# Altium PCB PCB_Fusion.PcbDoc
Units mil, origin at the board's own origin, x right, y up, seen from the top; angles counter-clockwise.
Board outline 985 x 1775 mil, 2 copper layers (Top Layer, Bottom Layer); 47 components, 34 nets, 181 pads, 49 vias.
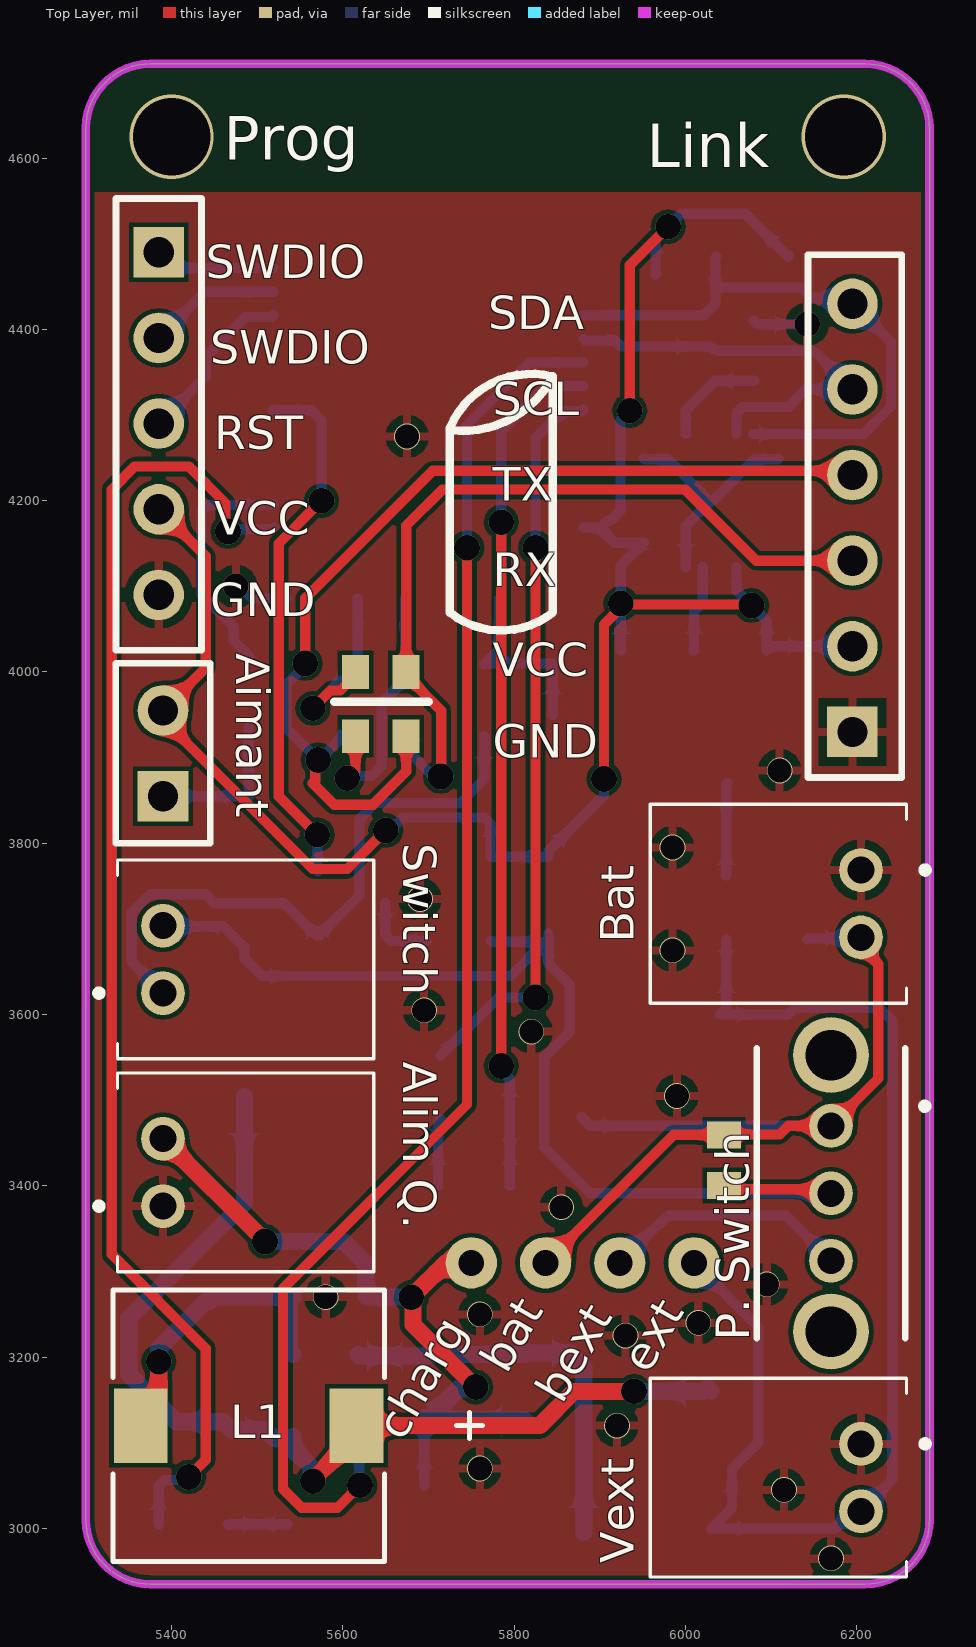
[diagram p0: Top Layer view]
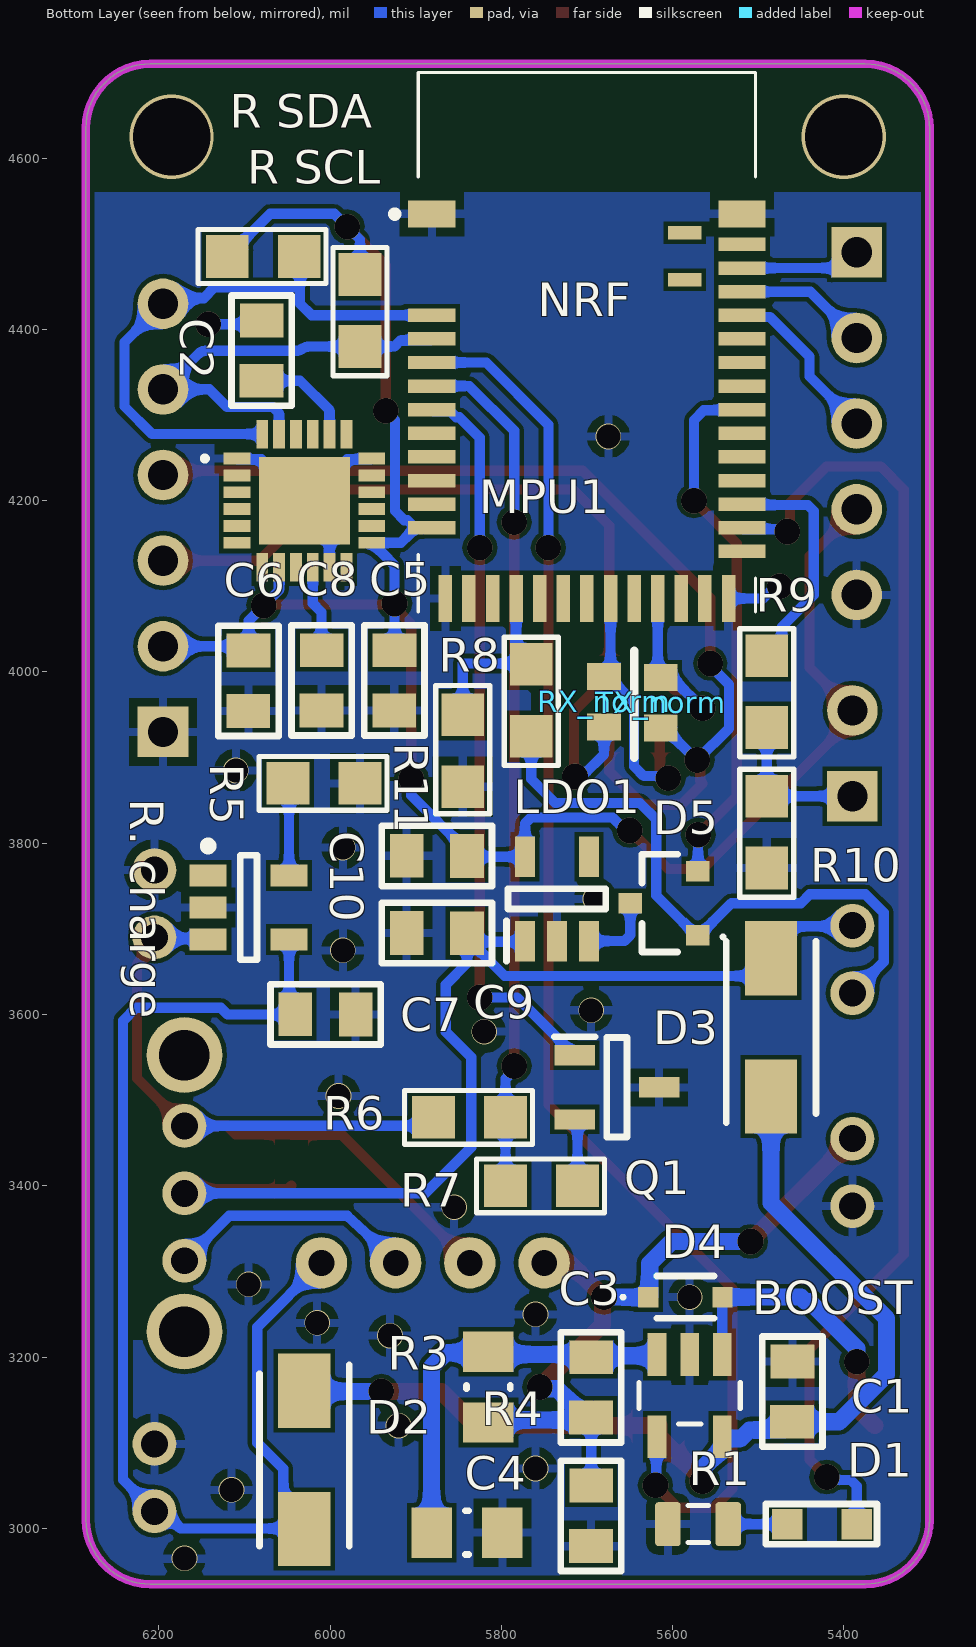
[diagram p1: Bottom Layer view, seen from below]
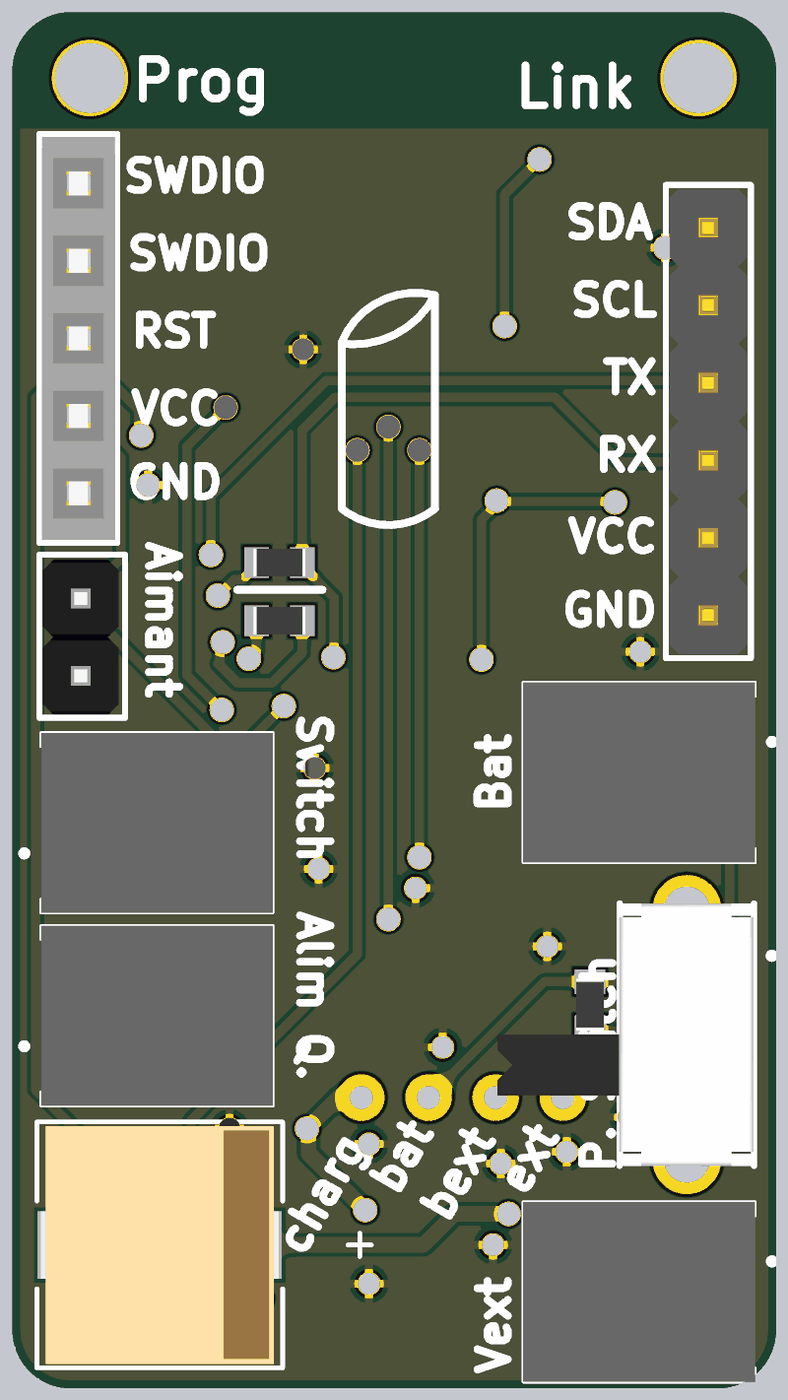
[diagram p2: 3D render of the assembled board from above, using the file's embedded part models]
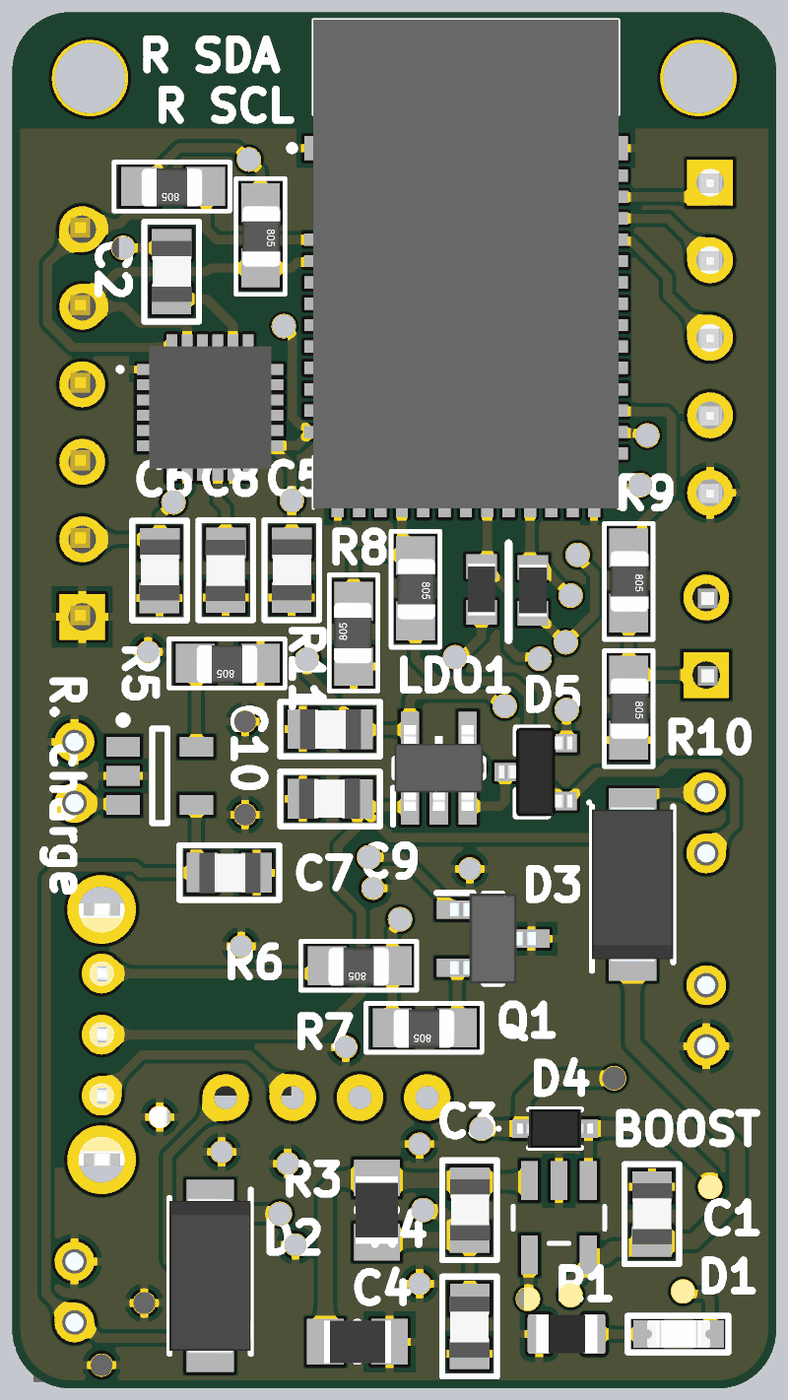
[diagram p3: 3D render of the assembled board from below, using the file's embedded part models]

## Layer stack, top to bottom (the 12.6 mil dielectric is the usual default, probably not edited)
Top Solder: solder mask 0.4, Solder Resist, Dk 3.5
Top Layer: signal copper 1.4
Dielectric 1: dielectric 12.6, FR-4, Dk 4.8
Bottom Layer: signal copper 1.4
Bottom Solder: solder mask 0.4, Solder Resist, Dk 3.5

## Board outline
5300,3010 5300,4635 cw(c5375,4635) 5375,4710 6210,4710 cw(c6210,4635) 6285,4635 6285,3010 cw(c6210,3010) 6210,2935 5375,2935 cw(c5375,3010)

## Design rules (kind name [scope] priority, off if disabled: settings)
Clearance [All] p1: gap=5 ignorepadtopadclearanceinfootprint=FALSE except(10: Arc-Via Track-Via Via-Via; 20: THPad-THPad)
PolygonConnect [All] p1: connectstyle=Relief reliefconductorwidth=10 reliefentries=4 polygonreliefangle="90 Angle" airgapwidth=10
RoutingVias [All] p1: holewidth=30 width=15 viastyle="Through Hole" minholewidth=30 minwidth=15 maxholewidth=40 maxwidth=30
SMDNeckDown [All] p1: percent=50.000
SolderMaskExpansion [All] p1: expansion=4 istentingtop=FALSE
Width [All] p1: maxlimit=20 minlimit=5 preferedwidth=12
30 further rules are at their usual default settings.

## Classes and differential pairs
component class Fusion: BOOST C1 C2 C3 C4 C5 C6 C7 C8 C9 C10 D1 D2 D3 D4 D5 L1 LDO1 MPU1 NRF Q1 R1 R3 R4 R5 R6 R7 R8 R9 R10 R11

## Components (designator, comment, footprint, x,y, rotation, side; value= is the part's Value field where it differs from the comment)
Aimant "JUMPER2" BARRETTE_2_M_D 5390,3855 r90 top (schematic designator "Switch magnetique1")
"Alim Q." "S2B-PH-K-S" S2BPHKS 5390,3376.26 r270 top (schematic designator Connecteur_Alim_Quille1)
Bat "S2B-PH-K-S" S2BPHKS 6205,3768.74 r90 top (schematic designator "Connecteur Bat")
BOOST "LM2735XMF" SOT95P285X110-5N 5580,3155 r270 bottom
C1 "CONDENSATEUR_CMS_CER_0805" CONDENSATEUR_CMS_0805 5460.39,3124.53 r90 bottom value=10uF
C2 "CONDENSATEUR_CMS_CER_0805" CONDENSATEUR_CMS_0805 6080,4340 r90 bottom value=2.2nF
C3 "CONDENSATEUR_CMS_CER_0805" CONDENSATEUR_CMS_0805 5695.39,3129.53 r90 bottom value=330pF
C4 "CONDENSATEUR_CMS_CER_0805" CONDENSATEUR_CMS_0805 5695,3050 r270 bottom value=10uF
C5 "CONDENSATEUR_CMS_CER_0805" CONDENSATEUR_CMS_0805 5925,3955 r90 bottom value=100nF
C6 "CONDENSATEUR_CMS_CER_0805" CONDENSATEUR_CMS_0805 6095.39,3954.53 r90 bottom value=10nF
C7 "CONDENSATEUR_CMS_CER_0805" CONDENSATEUR_CMS_0805 6040.47,3600.39 r180 bottom value=4.7uF
C8 "CONDENSATEUR_CMS_CER_0805" CONDENSATEUR_CMS_0805 6009.61,4025.47 r270 bottom value=100nF
C9 "CONDENSATEUR_CMS_CER_0805" CONDENSATEUR_CMS_0805 5840,3695 r0 bottom value=1uF
C10 "CONDENSATEUR_CMS_CER_0805" CONDENSATEUR_CMS_0805 5910.47,3785.39 r180 bottom value=4.7uF
D1 "LED_CMS_0805" LED_CMS_0805 5385,3005 r270 bottom
D2 "ES1D-E3_61T" DIOM5127X229N 6030,3080 r270 bottom
D3 "ES1D-E3_61T" DIOM5127X229N 5485,3585 r90 bottom
D4 "BAT165AX" BAT165AX 5585,3270 r180 bottom
D5 "BAT54C,215" BAT54C215 5610,3730 r90 bottom
L1 "1234659" IND_123_4659_RSP 5490,3120 r180 top
LDO1 "TPS76333DBVT" SOT95P280X145-5N 5735,3735 r90 bottom
Link "BARRETTE_6 CONTACTS_1 RANGEE_MALE_DROITE" BARRETTE_6_M_D 6195,3930 r90 top (schematic designator "Connecteur link")
MPU1 "MPU-6050" MPU6050 6030,4200 r180 bottom
NRF "MDBT42Q-512KV2" MDBT42Q512KV2 5700,4385 r180 bottom
"P. Switch" "OS102011MA1QN1" OS102011MA1QN1 6170,3391.26 r270 top (schematic designator "Interrupteur glissière?")
Prog "BARRETTE_5 CONTACTS_1 RANGEE_FEMELLE_DROITE" BARRETTE_5_F_D 5385,4490 r270 top (schematic designator "Connecteur prog1")
Q1 "TSM2312CX_RFG" SOT95P280X130-3N 5665,3515 r180 bottom
R1 "Resistor 1K +/-5% 0805 125 mW" RESC0805(2012)_L 5570,3005 r180 bottom value=150
R2 "Resistor 4k7 +/-1% 0603 100 mW" RESC1608X55X25ML10T15 6045,3430 r270 top value=0
R3 "Resistor 10k +/-1% 0805 125 mW" RESC2013X50X35ML15T15 5815,3165 r270 bottom value=3.3k
R4 "Resistor 10k +/-1% 0805 125 mW" RESC2013X50X35ML15T15 5840,2995 r0 bottom value=10k
R5 "RESISTANCE_CMS_0805" RESISTANCE_CMS_0805 5965,3870 r0 bottom value=2
R6 "RESISTANCE_CMS_0805" RESISTANCE_CMS_0805 5795,3480 r0 bottom value=100k
R7 "RESISTANCE_CMS_0805" RESISTANCE_CMS_0805 5711,3400 r0 bottom value=100k
R8 "RESISTANCE_CMS_0805" RESISTANCE_CMS_0805 5765,4009 r270 bottom value=100k
R9 "RESISTANCE_CMS_0805" RESISTANCE_CMS_0805 5490,4019 r270 bottom value=100
R10 "RESISTANCE_CMS_0805" RESISTANCE_CMS_0805 5490,3855 r270 bottom value=10k
R11 "RESISTANCE_CMS_0805" RESISTANCE_CMS_0805 5845,3866 r90 bottom value=100k
"R SCL" "RESISTANCE_CMS_0805" RESISTANCE_CMS_0805 5965,4464 r270 bottom value=10k (schematic designator "PULLUP SCL1")
"R SDA" "RESISTANCE_CMS_0805" RESISTANCE_CMS_0805 6036,4485 r0 bottom value=10k (schematic designator "PULLUP SDA1")
"R. charge" "MCP73831T-2DCI/OT" SOT-23-OT5_N 6095,3725 r180 bottom (schematic designator "Régulateur de charge")
RX_inv "Resistor 4k7 +/-1% 0603 100 mW" RESC1608X55X25ML10T15 5644.37,3925 r0 top value=0
RX_norm "Resistor 4k7 +/-1% 0603 100 mW" RESC1608X55X25ML10T15 5680,3965.47 r90 bottom value=0
Switch "S2B-PH-K-S" S2BPHKS 5390,3625 r270 top (schematic designator "Interrupteur Power")
TX_inv "Resistor 4k7 +/-1% 0603 100 mW" RESC1608X55X25ML10T15 5644.37,4000 r0 top value=0
TX_norm "Resistor 4k7 +/-1% 0603 100 mW" RESC1608X55X25ML10T15 5613.66,3964.13 r90 bottom value=0
Vext "S2B-PH-K-S" S2BPHKS 6205,3098.74 r90 top (schematic designator "Connecteur Vext")

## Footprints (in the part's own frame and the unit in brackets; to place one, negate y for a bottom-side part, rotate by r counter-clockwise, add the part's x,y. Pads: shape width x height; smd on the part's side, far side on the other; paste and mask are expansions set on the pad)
BARRETTE_2_M_D [mm] "BARRETTE 2 CONTACTS ; 1 RANGEE ; DROITE ; MALE ; ESPACEMENT BROCHES = 2.54 mm"
  rect 1.5x1.5 hole 0.9: 1(0,0)
  round 1.5 hole 0.9: 2(2.54,0)
  silkscreen extent -1.4,-1.4 3.94,1.4, body extent -1.3,-1.2 3.78,1.3, height 8.55
BARRETTE_5_F_D [mm] "BARRETTE 5 CONTACTS ; 1 RANGEE ; DROITE ; FEMELLE ; ESPACEMENT BROCHES = 2.54 mm"
  rect 1.5x1.5 hole 0.9: 1(0,0)
  round 1.5 hole 0.9: 2(2.54,0) 3(5.08,0) 4(7.62,0) 5(10.16,0)
  silkscreen extent -1.6,-1.27 11.8,1.27, body extent -1.5,-1.2 11.7,1.21, height 8.5
BARRETTE_6_M_D [mm] "BARRETTE 6 CONTACTS ; 1 RANGEE ; DROITE ; MALE ; ESPACEMENT BROCHES = 2.54 mm"
  rect 1.5x1.5 hole 0.9: 1(0,0)
  round 1.5 hole 0.9: 2(2.54,0) 3(5.08,0) 4(7.62,0) 5(10.16,0) 6(12.7,0)
  silkscreen extent -1.35,-1.46 14.15,1.32, body extent -1.22,-1.34 14.02,1.2, height 10.1
BAT54C215 [mm]
  rect 0.6x0.7 smd: 1(-0.95,-1) 2(0.95,-1) 3(0,1)
  silkscreen extent -1.45,-1.8 1.45,0.65, body extent -1.45,-1.2 1.45,1.2, height 0.95
BAT165AX [mm]
  rect 0.6x0.6 smd: 1(-1.1,0) 2(1.1,0)
  silkscreen extent -1.9,-0.62 0.85,0.62, body extent -1.24,-0.62 1.24,0.63, height 0.93
CONDENSATEUR_CMS_0805 [mm] "CONDENSATEUR CMS 0805 ; DIMENSIONS : 2mm x 1.25mm"
  rect 1x1.3 smd: 1(0,0) 2(1.79,-0.01)
  silkscreen extent -0.74,-0.9 2.53,0.89, body extent -0.09,-0.67 1.91,0.64, height 0.73
DIOM5127X229N [mm]
  rect 2.2x1.55 smd: 1(-2.05,0) 2(2.05,0)
  silkscreen extent -2.82,-1.33 2.55,1.33, body extent -2.55,-1.33 2.55,1.33, height 2.29
IND_123_4659_RSP [mil]
  rect 63x87 smd paste+0 mask+0: 1(-126,0) 2(126,0)
  silkscreen extent -273,-159 159,159, body extent -154,-154 154,154, height 199
LED_CMS_0805 [mm] "LED CMS 0805 ; DIMENSIONS : 2.0mm x 0.9mm"
  rect 0.9x0.9 smd: 1(0,0) 2(0,-2.062)
  silkscreen extent -0.6,-2.7 0.6,0.6, body extent -0.45,-2.06 0.45,0, height 0.85
MDBT42Q512KV2 [mm]
  rect 1.4x0.8 smd: 1(-4.6,3.8) 39(4.6,3.8)
  rect 1.4x0.4 smd: 2(-4.6,0.8) 3(-4.6,0.1) 4(-4.6,-0.6) 5(-4.6,-1.3) 6(-4.6,-2) 7(-4.6,-2.7) 8(-4.6,-3.4) 9(-4.6,-4.1) 10(-4.6,-4.8) 11(-4.6,-5.5) 25(4.6,-6.2) 26(4.6,-5.5) 27(4.6,-4.8) 28(4.6,-4.1) 29(4.6,-3.4) 30(4.6,-2.7) 31(4.6,-2) 32(4.6,-1.3) 33(4.6,-0.6) 34(4.6,0.1) 35(4.6,0.8) 36(4.6,1.5) 37(4.6,2.2) 38(4.6,2.9)
  rect 0.4x1.4 smd: 12(-4.2,-7.6) 13(-3.5,-7.6) 14(-2.8,-7.6) 15(-2.1,-7.6) 16(-1.4,-7.6) 17(-0.7,-7.6) 18(0,-7.6) 19(0.7,-7.6) 20(1.4,-7.6) 21(2.1,-7.6) 22(2.8,-7.6) 23(3.5,-7.6) 24(4.2,-7.6)
  rect 1x0.4 smd: 40(2.9,3.25) 41(2.9,1.85)
  silkscreen extent -5.8,-8 5,8, body extent -5,-8 5,8, height 2.3
MPU6050 [mm]
  rect 0.8x0.35 smd: 1(-2,1.25) 2(-2,0.75) 3(-2,0.25) 4(-2,-0.25) 5(-2,-0.75) 6(-2,-1.25) 13(2,-1.25) 14(2,-0.75) 15(2,-0.25) 16(2,0.25) 17(2,0.75) 18(2,1.25)
  rect 0.35x0.85 smd: 7(-1.25,-1.975) 8(-0.75,-1.975) 9(-0.25,-1.975) 10(0.25,-1.975) 11(0.75,-1.975) 12(1.25,-1.975) 19(1.25,1.975) 20(0.75,1.975) 21(0.25,1.975) 22(-0.25,1.975) 23(-0.75,1.975) 24(-1.25,1.975)
  rect 2.7x2.6 smd: 25(0,0)
  silkscreen extent -3,1.2 -2.9,1.3, body extent -2,-2 2,2, height 0.88
OS102011MA1QN1 [mm]
  round 1.3 hole 0.8: 1(-2,0) 2(0,0) 3(2,0)
  round 2.25 hole 1.5: 4(-4.1,0) 5(4.1,0)
  silkscreen extent -4.3,-2.2 4.3,2.88, body extent -4.3,-6.22 4.3,2.18, height 4.59
RESC0805(2012)_L [mm] "Chip Resistor, Body 2.0x1.3mm, IPC High Density"
  rrect25% 0.76x1.3 smd: 1(-0.9,0) 2(0.89,0)
  silkscreen extent -0.3,-0.55 0.3,0.55, body extent -1,-0.62 1,0.63, height 0.6
RESC1608X55X25ML10T15 [mm] "Chip Resistor, 2-Leads, Body 1.70x0.90mm, IPC Low Density"
  rect 0.8x1 smd: 1(-0.75,0) 2(0.75,0)
  body extent -0.85,-0.45 0.85,0.45, height 0.55
RESC2013X50X35ML15T15 [mm] "Chip Resistor, 2-Leads, Body 2.2x1.4mm, IPC Low Density"
  rect 1.2x1.5 smd: 1(-1.05,0) 2(1.05,0)
  silkscreen extent -0.05,-0.65 0.05,0.65, body extent -1.1,-0.7 1.1,0.7, height 0.5
RESISTANCE_CMS_0805 [mil] "RESISTANCE CMS 0805 ; DIMENSIONS : 2mm x 1.25mm"
  rect 50x50 smd: 1(0,0) 2(84,0)
  silkscreen extent -31,-31 118,31, body extent 4,-24 83,26, height 31
S2BPHKS [mm]
  round 1.3 hole 0.8: 1(0,0) 2(-2,0)
  silkscreen extent -3.95,-2 1.95,6.25, body extent -3.95,-1.35 1.95,6.25, height 4.9
SOT95P280X130-3N [mm]
  rect 1.2x0.6 smd: 1(-1.25,0.95) 2(-1.25,-0.95) 3(1.25,0)
  silkscreen extent -1.85,-1.47 0.3,1.5, body extent -1.4,-1.47 1.4,1.47, height 1.3
SOT95P280X145-5N [mm]
  rect 1.2x0.6 smd: 1(-1.25,0.95) 2(-1.25,0) 3(-1.25,-0.95) 4(1.25,-0.95) 5(1.25,0.95)
  silkscreen extent -1.85,-1.45 0.3,1.5, body extent -1.4,-1.45 1.4,1.45, height 1.2
SOT95P285X110-5N [mil]
  rect 50x22 smd: 1(-48,38) 2(-48,0) 3(-48,-38) 4(48,-38) 5(48,38)
  silkscreen extent -15,-59 33,59
SOT-23-OT5_N [mm] "SOT23, 5-Leads, Body 2.9x1.6mm, Pitch 0.95mm, Lead Span 2.7mm, IPC Medium Density"
  rect 1.1x0.65 smd: 1(-1.2,0.95) 2(-1.2,0) 3(-1.2,-0.95) 4(1.2,-0.95) 5(1.2,0.95)
  silkscreen extent -1.33,-1.55 0.25,1.95, body extent -0.9,-1.55 0.9,1.55, height 1.45

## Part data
Aimant: library part CMP-039-0004-1, "BARRETTE 2 CONTACTS 1 RANGEE MALE DROITE"
"Alim Q." Bat Switch Vext: "Connector", Manufacturer_Name="JST (JAPAN SOLDERLESS TERMINALS)"
BOOST: "Integrated Circuit", Manufacturer_Name="Texas Instruments"
C1 C2 C3 C4 C5 C6 C7 C8 C9 C10: library part CMP-038-0003-1, "CONDENSATEUR CMS CERAMIQUE 0805"
D1: library part CMP-024-0003-1, "LED CMS 0805"
D2 D3: "Diode", Arrow Part Number=ES1D-E3/61T, Manufacturer_Name=Vishay, Mouser Part Number=625-ES1D-E3
D4: "Schottky Diode", Manufacturer_Name=Nexperia, Mouser Part Number=771-BAT165AX
D5: "Schottky Diode", Manufacturer_Name=Nexperia, Mouser Part Number=771-BAT54C-T/R
L1: "No Description Available", Mfr_Name="RS Pro"
LDO1: "Integrated Circuit", Manufacturer_Name="Texas Instruments", Mouser Part Number=595-TPS76333DBVT
Link: library part CMP-039-0125-1, "BARRETTE 6 CONTACTS 1 RANGEE MALE DROITE"
MPU1: "Integrated Circuit", Manufacturer_Name=TDK, Mouser Part Number=410-MPU-6050
NRF: "Integrated Circuit", Manufacturer_Name=Raytac
"P. Switch": "Switch", Manufacturer_Name="C & K COMPONENTS", Mouser Part Number=611-OS102011MA1QN1
Prog: library part CMP-039-0118-1, "BARRETTE 5 CONTACTS 1 RANGEE FEMELLE DROITE"
Q1: "MOSFET (N-Channel)", Arrow Part Number="TSM2312CX RFG", Manufacturer_Name="Taiwan Semiconductor", Mouser Part Number=821-TSM2312CXRFG
R1: library part CMP-009-00118-3, "Chip Resistor, 1 kOhms, +/-5%, 125 mW, -55 to 155 degC, 0805", Case/Package=0805, Max Operating Temperature=155°C, Min Operating Temperature=-55°C, Power=125mW, Tolerance=5%
R2 RX_inv RX_norm TX_inv TX_norm: library part CMP-009-00031-5, "Chip Resistor, 4.7 KOhm, +/- 1%, 0.1 W, -55 to 155 degC, 0603 (1608 Metric)", Case/Package=0603, Max Operating Temperature=155°C, Min Operating Temperature=-55°C, Power=100mW, Tolerance=1%
R3 R4: library part CMP-009-00018-5, "Chip Resistor, 10 KOhm, +/- 1%, 125 mW, -55 to 155 degC, 0805 (2012 Metric)", Case/Package=0805, Max Operating Temperature=155°C, Min Operating Temperature=-55°C, Power=125mW, Tolerance=1%, Voltage Rating=150V
R5 R6 R7 R8 R9 R10 R11 "R SCL" "R SDA": library part CMP-037-0001-1, "RESISTANCE CMS 0805"
"R. charge": library part CMP-045-0000-1, "Miniature Single-Cell, Fully Integrated Li-Ion, Li-Polymer Charge Management Controller, 4.2V, 5-Pin SOT-23, Industrial Temperature, Tape and Reel", Manufacturer=Microchip

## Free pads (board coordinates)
  round 60 hole 30: 2(5923.33,3310) 3(5836.67,3310) 5(5750,3310) 6(6010,3310)

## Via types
v1: diameter 30, hole 30, Top Layer to Bottom Layer, 29 vias
v2: diameter 30, hole 28, Top Layer to Bottom Layer, 18 vias
v3: diameter 98.43, hole 90.55, Top Layer to Bottom Layer, 2 vias

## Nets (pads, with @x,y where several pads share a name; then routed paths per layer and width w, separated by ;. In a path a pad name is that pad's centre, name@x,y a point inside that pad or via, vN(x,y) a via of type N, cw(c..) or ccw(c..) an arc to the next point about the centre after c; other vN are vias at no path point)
Aimant: NRF.27 R9.1 | length 279
  Bottom Layer w12: R9.1 5472.27,4036.73 5472.27,4052.73 5435,4090 5435,4187.97 5442.03,4195 5517.87,4195 NRF.27
"EN lecture bat": NRF.6 Q1.1 | length 862
  Top Layer w12: v1(5825,3620) v1(5825,4145)
  Bottom Layer w12: Q1.1 5781.81,3620 v1(5825,3620) ; v1(5825,4145) 5825,4273.59 5848.99,4297.57 5852.73,4297.57 5859.54,4304.39 5879.23,4304.39 NRF.6
EN_Alim_quilles: BOOST.4 NRF.4 | length 1665.5
  Top Layer w12: v1(5620.05,3050.35) 5593.7,3024 5552.16,3024 5530,3046.16 5530,3280 5745,3495 v1(5745,4145)
  Bottom Layer w12: BOOST.4 5619.02,3105.97 5619.02,3051.37 v1(5620.05,3050.35) ; v1(5745,4145) 5745,4288.84 5817.54,4361.38 NRF.4
GND: "Alim Q..1" "R. charge.2" Bat.1 BOOST.2 C1.2 C2.2 C4.2 C5.1 C6.1 C7.2 C8.2 C9.2 C10.1 LDO1.2 Link.1 MPU1.1 MPU1.11 MPU1.18 MPU1.25 NRF.1 NRF.12 NRF.24 NRF.39 Prog.5 Q1.3 R1.1 R4.1 R5.1 R10.2 R11.1 Vext.1 | length 418.1
  Bottom Layer w12: v1(5475,4100) 5479.87,4100 5494.08,4085.79 NRF.24 ; MPU1.18 5952.15,4248.32 5979.71,4248.32 6028.03,4200 MPU1.25 ; MPU1.11 6000.47,4170.47 MPU1.25 ; C2.2 6084.08,4406 v1(6142.08,4406) ; MPU1.1 6107.85,4248.32 6080.29,4248.32 6031.97,4200 MPU1.25
  other v2: 6170,2965 6115,3045 5760,3070 5920,3120 5930,3225 6015,3240 5760,3250 5580,3270 6095,3285 5855,3375 5990,3505 5820,3580 5695,3605 5985,3675 5690,3735 5985,3795 6110,3885 5675,4275
"Lecture Vbat": NRF.5 R6.1 R7.2 | length 1003.5
  Top Layer w12: v1(5785,3540) v1(5785,4175)
  Bottom Layer w12: v1(5785,3540) 5785,3535.13 5795,3525.13 R6.1 R7.2 ; v1(5785,4175) 5785,4281.63 5837.18,4333.82 NRF.5
LED: D1.1 NRF.26 | length 1541.7
  Top Layer w12: v1(5420,3060) 5440,3080 5440,3210 5330,3320 5330,4212.97 5357.03,4240 5420,4240 5463,4197 5463,4167 v1(5466,4164)
  Bottom Layer w12: D1.1 5385,3049.53 5392.03,3056.56 5416.56,3056.56 v1(5420,3060) ; v1(5466,4164) 5468.59,4166.59 5517.02,4166.59 NRF.26
NetBOOST_1: BOOST.1 D4.2 L1.2 | length 347.4
  Top Layer w20: L1.2 5385,3141 v1(5385,3194.75)
  Bottom Layer w12: BOOST.1@5541.85,3203.15 D4.2@5541.85,3269.85
  Bottom Layer w20: v1(5385,3194.75) 5385,3210 5440,3265 5445,3265 5450,3270 D4.2 D4.2@5541.85,3269.85 ; BOOST.1@5541.85,3203.15 BOOST.1
NetBOOST_3: BOOST.3 C3.2 R3.1 R4.2 | length 468.5
  Bottom Layer w20: BOOST.3 5618,3202.5 5619,3201.5 5693.5,3201.5 C3.2 5698.17,3203.17 5811.83,3203.17 R3.1 5816.34,3205 5865,3205 5881.34,3188.66 R4.2
NetBOOST_5: BOOST.5 C1.1 D2.1 D3.1 L1.1 | length 1185.8
  Top Layer w20: v1(5565,3055) 5565,3057 5616,3108 L1.1 5830,3120 5870,3160 v1(5940,3160)
  Bottom Layer w20: D3.1 5485,3380 5350,3245 5350,3180 5405.47,3124.53 C1.1 5470.08,3114.84 5510.16,3114.84 5520,3105 5541,3105 BOOST.5@5542,3106 ; BOOST.5 BOOST.5@5542,3106 ; v1(5565,3055) 5563.09,3056.91 5563.09,3071.91 5542,3093 BOOST.5@5542,3106 ; v1(5940,3160) 6020.71,3160 6025.71,3165 D2.1
NetC2_1: C2.1 MPU1.20 | length 121.5
  Bottom Layer w12: MPU1.20 6000.47,4305.47 6035,4340 C2.1
NetC8_1: C8.1 MPU1.10 | length 101.1
  Bottom Layer w12: C8.1 6010,4025.87 6010,4070 6020.16,4080.16 MPU1.10
NetD1_2: D1.2 R1.2 | length 68.8
  Bottom Layer w12: D1.2 R1.2
NetD5_1: D5.1 R8.2 Switch.1 | length 726.9
  Bottom Layer w12: Switch.1 5353.41,3661.59 5353.41,3718.9 5374.84,3740.33 5439.67,3740.33 5450,3730 5531.26,3730 5568.66,3692.6 D5.1 5572.6,3692.6 5619,3739 5619,3827.84 5638.16,3847 5737,3847 5765,3875 R8.2
NetD5_3: D5.3 LDO1.3 | length 88.3
  Bottom Layer w12: D5.3 5649.37,3692.82 5656.4,3685.79 LDO1.3
NetQ1_2: Q1.2 R7.1 | length 78.9
  Bottom Layer w12: R7.1 5711,3474.39 Q1.2
NetR5_2: "R. charge.5" R5.2 | length 108.1
  Bottom Layer w12: 6047.76,3762.4 6047.76,3868.76 R5.2
NetR9_2: Aimant.1 R9.2 R10.1 | length 180
  Bottom Layer w12: Aimant.1 R10.1 R9.2
Power: NRF.15 R8.1 R11.2 | length 223.1
  Bottom Layer w12: R8.1 R8.1@5766,4010 ; NRF.15 5782.68,4026.68 R8.1@5766,4010 ; R11.2 5845,4010 R8.1@5766,4010
RESET: NRF.35 Prog.3 | length 199.8
  Bottom Layer w12: Prog.3 5440,4345 5440,4368.1 5486.52,4414.62 5517.02,4414.62 NRF.35
RX: NRF.19 RX_inv.1 RX_norm.2 | length 307.2
  Top Layer w12: v1(5605,3876) 5606,3876 5614.84,3884.84 RX_inv.1
  Bottom Layer w12: v1(5605,3876) 5607.44,3878.44 5633.44,3878.44 5645,3890 5645,3965 5646.06,3965 5672.44,3991.38 NRF.19
RX_out: Link.3 RX_norm.1 TX_inv.2 | length 960.1
  Top Layer w12: v1(5714,3878) 5715,3879 5715,3954.96 5673.9,3996.06 TX_inv.2 5673.9,4171.06 5715.84,4213 5999.71,4213 6082.71,4130 Link.3
  Bottom Layer w12: RX_norm.1 5680,3904 5704.56,3879.44 5712.56,3879.44 v1(5714,3878)
SCL: "R SCL.2" Link.5 MPU1.23 NRF.3 | length 508.3
  Bottom Layer w12: NRF.3 5882.98,4387.06 5917.94,4387.06 5925,4380 6024.72,4380 cw(c6024.72,4368) 6031,4378.23 6033.42,4376.75 ccw(c6039.66,4387) 6039.66,4375 6145.03,4375 cw(c6145.03,4363) 6153.51,4371.49 Link.5 6140.83,4330 6120.15,4309.31 6066.56,4309.31 6059.53,4302.29 MPU1.23
SDA: "R SDA.1" Link.6 MPU1.24 NRF.2 | length 696
  Bottom Layer w12: NRF.2 6021.5,4416.5 6035,4430 6035,4450 ; 6036,4485 6035,4484 6035,4450 ; MPU1.24 6207.76,4277.76 6240,4310 6240,4385 Link.6 6188.47,4436.53 6147.47,4436.53 6135,4449 6036,4449 6035,4450
Shutdown: D5.2 NRF.31 | length 628.3
  Top Layer w12: v1(5570,3810) 5525,3855 5525,4150 v1(5575,4200)
  Bottom Layer w12: NRF.31@5518.27,4305.63 NRF.31 5519.53,4305.63 5563.45,4305.63 5575,4294.08 v1(5575,4200) ; v1(5570,3810) 5570.31,3809.68 5570.31,3767.72 D5.2
SWDCLK: NRF.36 Prog.2 | length 156.3
  Bottom Layer w12: Prog.2 5439.06,4444.06 NRF.36
SWDIO: NRF.37 Prog.1 | length 141.5
  Bottom Layer w12: Prog.1 5403.39,4471.61 NRF.37
TX: NRF.21 TX_inv.1 TX_norm.2 | length 227
  Top Layer w12: v1(5565,3957.5) 5585.94,3978.44 5597.22,3978.44 5614.84,3996.06 TX_inv.1
  Bottom Layer w12: v1(5565,3957.5) 5597.5,3990 5610,3990 TX_norm.2 5617.32,3997.32 NRF.21
TX_out: Link.4 RX_inv.2 TX_norm.1 | length 1180.3
  Top Layer w12: v1(5556,4010) 5556,4086 5705,4235 6190,4235 Link.4 ; v1(5571.15,3897.31) 5567.7,3893.86 5567.7,3872.7 5565,3870 5590,3845 5635,3845 5673.9,3883.9 RX_inv.2
  Bottom Layer w12: v1(5556,4010) 5556,4007.33 5534,3985.33 5534,3934.45 v1(5571.15,3897.31) 5572.42,3897.31 5609.72,3934.61 TX_norm.1
Vbat_Ext: "P. Switch.3" pad.2 | length 293.1
  Bottom Layer w12: pad.2@5920,3310 5980,3365 6117.52,3365 6170,3312.52
Vbat_In: "P. Switch.1" "R. charge.3" Bat.2 pad.3 R2.1 R6.2 | length 1009.8
  Top Layer w12: pad.3 5986.19,3459.53 R2.1 6045.47,3460 6110,3460 6120,3470 6170,3470 6225.29,3525.29 6225.29,3659.11 6205,3679.4 Bat.2
  Bottom Layer w12: R6.2 5889,3470 6170,3470 ; 6142.24,3687.6 6143.44,3688.8 6203.8,3688.8 Bat.2
Vbat_Out: "P. Switch.2" C9.1 D3.2 LDO1.1 R2.2 Switch.2 | length 1316.9
  Top Layer w12: R2.2 6049.61,3395.87 6165.39,3395.87 6170,3391.26
  Bottom Layer w12: Switch.2 5390.72,3703.02 5460.49,3703.02 5485,3678.5 D3.2 5505.71,3645 5795.91,3645 5832.95,3682.05 C9.1@5840,3689.09 ; LDO1.1 5774.21,3685.79 5775,3685 C9.1@5830,3685 ; C9.1 C9.1@5840,3689.09 ; 6170,3391.26 5888.74,3391.26 5835,3445 5835,3550 5865,3580 5865,3635 5840,3660 C9.1@5840,3689.09
VCC: "R SCL.1" "R SDA.2" Aimant.2 C5.2 C6.2 C10.2 LDO1.5 Link.2 MPU1.8 MPU1.13 NRF.11 Prog.4 | length 2406.1
  Top Layer w12: Prog.4 5440,4135 5440,4005 Aimant.2 5390,3945 5565,3770 5605,3770 v1(5650,3815) ; v1(5905,3875) 5905,4055.52 5925.74,4076.26 5925.74,4078.87 6076.13,4078.87 v1(6077.26,4077.74) ; v1(5935,4305) 5935,4475 v1(5980,4520)
  Bottom Layer w12: v1(5650,3815) 5653.44,3818.44 5658.44,3818.44 5670,3830 5765.37,3830 5772.4,3822.97 LDO1.5 5839.21,3784.21 C10.2 5840,3790.91 5905,3855.91 v1(5905,3875) ; NRF.11 NRF.11@5900.79,4168.46 ; C5.2 v1(5924.61,4080) 5924.61,4124.13 MPU1.13 5917.51,4150.79 5902.66,4165.64 5902.66,4166.59 NRF.11@5900.79,4168.46 ; v1(5935,4305) 5924.11,4294.11 5924.11,4188.04 5913.22,4177.15 5909.47,4177.15 NRF.11@5900.79,4168.46 ; 5966,4465 5965,4464 5965,4505 v1(5980,4520) 5995,4535 6070,4535 6120,4485 6121,4486 ; MPU1.8 6059.53,4095.47 v1(6077.26,4077.74) 6095,4060 C6.2 6100,4030 Link.2
Vchargement: "Alim Q..2" C3.1 C4.1 D4.1 pad.5 R3.2 | length 887.7
  Top Layer w20: 5390,3455 5390,3454.5 5509,3335.5 v1(5509,3335) ; pad.5 5720,3310 v1(5680,3270) 5681.91,3268.09 5681.91,3238.09 v1(5755,3165)
  Bottom Layer w12: C4.1 C3.1@5695,3129.13
  Bottom Layer w20: v1(5509,3335) 5601.07,3335 5626.65,3309.42 5626.65,3271.65 D4.1 v1(5680,3270) ; C3.1@5695,3129.13 5697.54,3126.59 5812.07,3126.59 R3.2 ; C3.1 5701.3,3129.53 5734.86,3163.09 5753.09,3163.09 v1(5755,3165)
Vext: "R. charge.4" C7.1 D2.2 pad.6 Vext.2 | length 1436.3
  Bottom Layer w12: pad.6 6085,3235 6085,3100 6054.51,3069.51 6054.51,3023.8 D2.2@6030.71,3000 ; D2.2 D2.2@6030.71,3000 ; 6047.76,3687.6 6047.76,3607.68 C7.1 6040.87,3600 6119.55,3600 6127.51,3607.97 6226.59,3607.97 6241.59,3592.97 6241.59,3056.59 Vext.2 6194.4,3020 6174.4,3000 D2.2@6030.71,3000
pads on no net: "P. Switch.4" "P. Switch.5" "R. charge.1" LDO1.4 MPU1.2 MPU1.3 MPU1.4 MPU1.5 MPU1.6 MPU1.7 MPU1.9 MPU1.12 MPU1.14 MPU1.15 MPU1.16 MPU1.17 MPU1.19 MPU1.21 MPU1.22 NRF.7 NRF.8 NRF.9 NRF.10 NRF.13 NRF.14 NRF.16 NRF.17 NRF.18 NRF.20 NRF.22 NRF.23 NRF.25 NRF.28 NRF.29 NRF.30 NRF.32 NRF.33 NRF.34 NRF.38 NRF.40 NRF.41
copper on no net:
  other v3: 5400,4625 6185,4625

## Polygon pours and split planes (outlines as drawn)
GND on Top Layer "TOP_GND" (solid, remove dead copper, pour order 1): 5300,4710 5300,2935 6285,2935 6285,4710
GND on Bottom Layer "BTM_GND" (solid, remove dead copper, pour order 0): 5300,4710 5300,2935 6285,2935 6285,4710

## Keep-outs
Keep-Out Layer:
  the board outline again, w10

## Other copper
Top Layer:
  pour cut-out: 5300,4710 6285,4710 6285,4560 5300,4560
Bottom Layer:
  pour cut-out: 6170,3391.26 6163.74,3385 6110,3385 6110,3372.52 6175,3307.52 6175,3220 6240,3220 6245,3225 6245,3420 6180,3420 6175,3415
  pour cut-out: 6177.05,3607.97 6226.59,3607.97 6241.59,3592.97 6240,3591.38 6240,3435 6175,3435 6170,3440
  pour cut-out: 5785,3995 5765,3975 5765,3875 5750,3875 5725,3850 5650,3925 5650,4035 5680,4065 5688.77,4056.23 5782.68,4056.23
  pour cut-out: 5910,4380 5915,4375 6075,4375 6075,4345 5985,4255 5930,4255 5930,4285 5910,4305
  pour cut-out: 5845,3450 5900,3395 6175,3395 6180,3400 6170,3410 6170,3470 5855,3470
  pour cut-out: 5300,4710 5300,4560 6285,4560 6285,4710

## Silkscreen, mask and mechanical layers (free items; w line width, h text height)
Top Overlay:
  lines w10: 5590,3965 5700,3965 ; 5724.67,4282.46 ccw(c5740,4400) 5845,4345 ; 5725,4069.34 ccw(c5785,4145) 5845.32,4069.59 ; 5725,4070 5725,4282.46 ; 5725,4285 cw(c5820,4245) 5845,4345 ; 5845,4070 5845,4345
  text "SWDIO" at 5440,4460 h39.37
  text "SDA" at 5770,4400 h39.37
  text "SWDIO" at 5445,4360 h39.37
  text "SCL" at 5775,4300 h39.37
  text "RST" at 5450,4260 h39.37
  text "TX" at 5775,4200 h39.37
  text "VCC" at 5450,4160 h39.37
  text "RX" at 5775,4100 h39.37
  text "GND" at 5445,4065 h39.37
  text "VCC" at 5775,3995 h39.37
  text "GND" at 5775,3900 h39.37
  text "bat" at 5791.34,3178.66 h39.37 r60
  text "ext" at 5956.34,3178.66 h39.37 r60
  text "bext" at 5856.34,3143.66 h39.37 r60
  text "charg" at 5669.98,3100.22 h39.37 r60
Bottom Overlay:
  lines w10: 5645,3900 5645,4025
Mechanical 13:
  rectangle: 5065,2776.5 6246.1,4745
